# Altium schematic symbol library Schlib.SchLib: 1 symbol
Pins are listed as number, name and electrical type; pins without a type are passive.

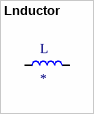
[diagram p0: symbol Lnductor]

## Lnductor
designator L
pins: 1, 2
